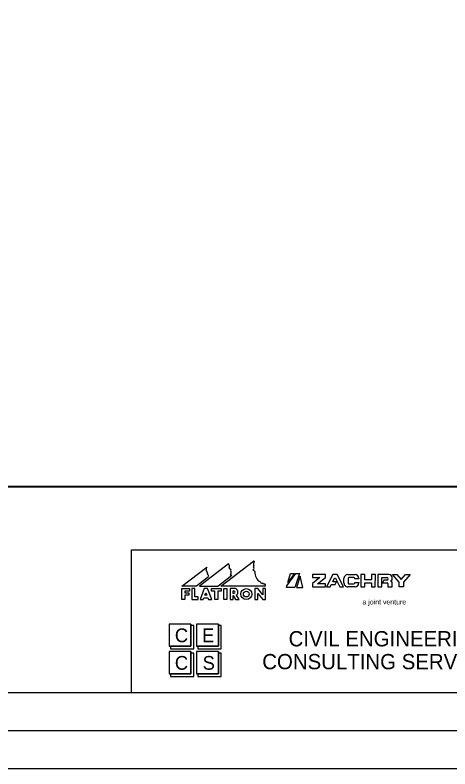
# Model space of a CAD drawing. Extents: x -2251 to 10196, y -13470 to 1199.
# Drawn here: x 3737.4 to 4022.4, y -4450.7 to -3956.7 of the extents above; entities that cross this region are included whole.
import ezdxf

# ---------------------------------------------------------------- set-up
doc = ezdxf.new("R2010")
doc.units = 0
for name, color, linetype in [('Level 3', 7, 'Continuous'), ('RD_SHT_Bndy', 7, 'Continuous'), ('RD_SHT_Iplotshp', 7, 'Continuous'), ('RD_SHT_Logo', 7, 'Continuous'), ('RD_SHT_Misc1', 7, 'Continuous'), ('RD_SHT_Snap', 7, 'Continuous'), ('RD_SHT_TX', 7, 'Continuous'), ('RD_TX_RoadID', 7, 'Continuous')]:
    doc.layers.add(name, color=color, linetype=linetype)

msp = doc.modelspace()

# ---------------------------------------------------------------- linework, layer by layer
at = {"layer": 'Level 3'}
msp.add_line((3965.07, -4363.99), (3965.07, -4363.99), dxfattribs=at)
msp.add_line((3965.07, -4363.99), (3965.07, -4363.99), dxfattribs=at)
msp.add_line((3965.07, -4363.99), (3965.07, -4363.99), dxfattribs=at)
msp.add_line((3965.07, -4363.99), (3965.07, -4363.99), dxfattribs=at)
at = {"layer": 'RD_SHT_Bndy'}
for p, q in [((2603.1, -4400.65), (4278.1, -4400.65)), ((4291.65, -4425.65), (2531.65, -4425.65)), ((4291.6, -4450.7), (2531.6, -4450.65))]:
    msp.add_line(p, q, dxfattribs=at)
msp.add_lwpolyline([(2653.4, -3401.26), (4231.08, -3401.26), (4231.08, -4265.57), (2653.4, -4265.57)], close=True, dxfattribs=at)
at = {"layer": 'RD_SHT_Iplotshp'}
msp.add_lwpolyline([(2496.65, -3325.65), (4296.65, -3325.65), (4296.65, -4425.65), (2496.65, -4425.65)], close=True, dxfattribs=at)
at = {"layer": 'RD_SHT_Logo'}
for p, q in [((3877.35, -4316.27), (3858.31, -4330.86)), ((3872.32, -4330.86), (3893.74, -4314.44)), ((3846.7, -4330.86), (3862.98, -4318.38)), ((3915.56, -4330.77), (3921.47, -4322.59)), ((3920.48, -4322.59), (3916.24, -4328.47)), ((3916.24, -4328.47), (3917.96, -4322.59)), ((3917.96, -4322.59), (3920.48, -4322.59)), ((3923.82, -4322.59), (3920.68, -4331.76)), ((3921.47, -4322.59), (3923.82, -4322.59)), ((3864.27, -4324.74), (3856.29, -4330.86)), ((3870.3, -4330.86), (3879.48, -4323.82)), ((3924.24, -4324.44), (3921.74, -4331.76)), ((3925.99, -4331.76), (3924.24, -4324.44)), ((3940.93, -4323.35), (3932.22, -4323.35)), ((3932.22, -4323.35), (3932.22, -4325.3)), ((3937.2, -4325.3), (3932.22, -4329.24)), ((3932.22, -4325.3), (3937.2, -4325.3)), ((3935.63, -4329.35), (3940.93, -4325.16)), ((3940.93, -4325.16), (3940.93, -4323.35)), ((3945.58, -4323.35), (3941.53, -4331.3)), ((3945.57, -4327.99), (3946.71, -4325.75)), ((3948.58, -4323.35), (3945.58, -4323.35)), ((3946.71, -4325.75), (3947.44, -4325.75)), ((3947.44, -4325.75), (3950.27, -4331.3)), ((3952.63, -4331.3), (3948.58, -4323.35)), ((3952.94, -4328.8), (3952.94, -4325.85)), ((3955.44, -4323.35), (3960.18, -4323.35)), ((3955.64, -4325.8), (3955.64, -4328.85)), ((3959.48, -4325.3), (3956.14, -4325.3)), ((3959.98, -4326.15), (3959.98, -4325.8)), ((3962.68, -4326.15), (3959.98, -4326.15)), ((3962.68, -4325.85), (3962.68, -4326.15)), ((3966.62, -4323.35), (3964.02, -4323.35)), ((3964.02, -4323.35), (3964.02, -4331.3)), ((3966.62, -4326.8), (3966.62, -4323.35)), ((3970.9, -4326.8), (3966.62, -4326.8)), ((3970.9, -4323.35), (3970.9, -4326.8)), ((3973.51, -4323.35), (3970.9, -4323.35)), ((3973.5, -4331.3), (3973.51, -4323.35)), ((3982.43, -4323.35), (3975.13, -4323.35)), ((3975.13, -4323.35), (3975.13, -4331.3)), ((3977.83, -4331.3), (3977.83, -4325.31)), ((3977.83, -4325.31), (3981.07, -4325.31)), ((3979.03, -4326.97), (3978.11, -4328.77)), ((3981.07, -4326.97), (3979.03, -4326.97)), ((3983.68, -4327.6), (3983.68, -4327.47)), ((3984.43, -4326.36), (3984.43, -4325.35)), ((3984.68, -4323.35), (3987.64, -4323.35)), ((3989.08, -4328.24), (3984.68, -4323.35)), ((3987.64, -4323.35), (3990.48, -4326.51)), ((3990.48, -4326.51), (3993.32, -4323.35)), ((3996.28, -4323.35), (3991.88, -4328.24)), ((3993.32, -4323.35), (3996.28, -4323.35)), ((3856.29, -4330.86), (3846.7, -4330.86)), ((3846.72, -4339.7), (3846.72, -4332.5)), ((3846.72, -4332.5), (3851.82, -4332.5)), ((3851.82, -4332.5), (3851.82, -4334.15)), ((3855.12, -4332.5), (3853.17, -4332.5)), ((3853.17, -4332.5), (3853.17, -4339.7)), ((3855.12, -4337.9), (3855.12, -4332.5)), ((3858.31, -4330.86), (3870.3, -4330.86)), ((3861.42, -4332.5), (3858.65, -4339.71)), ((3863.52, -4332.5), (3861.42, -4332.5)), ((3866.28, -4339.71), (3863.52, -4332.5)), ((3866.22, -4334.15), (3866.22, -4332.5)), ((3866.22, -4332.5), (3872.37, -4332.5)), ((3901.19, -4330.86), (3872.32, -4330.86)), ((3872.37, -4332.5), (3872.37, -4334.15)), ((3874.17, -4339.71), (3874.17, -4332.5)), ((3874.17, -4332.5), (3876.12, -4332.5)), ((3876.12, -4332.5), (3876.12, -4339.71)), ((3881.8, -4332.5), (3878.38, -4332.5)), ((3878.38, -4332.5), (3878.38, -4339.71)), ((3896.52, -4332.5), (3894.57, -4332.5)), ((3894.57, -4332.5), (3894.57, -4339.71)), ((3899.67, -4336.53), (3896.52, -4332.5)), ((3901.62, -4332.5), (3899.67, -4332.5)), ((3899.67, -4332.5), (3899.67, -4336.53)), ((3901.62, -4339.71), (3901.62, -4332.5)), ((3915.27, -4331.76), (3915.56, -4330.77)), ((3920.68, -4331.76), (3915.27, -4331.76)), ((3921.74, -4331.76), (3925.99, -4331.76)), ((3932.22, -4329.24), (3932.22, -4331.3)), ((3932.22, -4331.3), (3940.93, -4331.3)), ((3940.93, -4329.35), (3935.63, -4329.35)), ((3940.93, -4331.3), (3940.93, -4329.35)), ((3941.53, -4331.3), (3943.88, -4331.3)), ((3943.88, -4331.3), (3944.65, -4329.79)), ((3944.65, -4329.79), (3947.23, -4329.79)), ((3948.15, -4327.99), (3945.57, -4327.99)), ((3947.23, -4329.79), (3948.15, -4327.99)), ((3950.27, -4331.3), (3952.63, -4331.3)), ((3960.18, -4331.3), (3955.44, -4331.3)), ((3956.14, -4329.35), (3959.48, -4329.35)), ((3959.98, -4328.5), (3962.68, -4328.5)), ((3959.98, -4328.85), (3959.98, -4328.5)), ((3962.68, -4328.5), (3962.68, -4328.8)), ((3964.02, -4331.3), (3966.62, -4331.3)), ((3966.62, -4331.3), (3966.62, -4328.8)), ((3966.62, -4328.8), (3970.9, -4328.8)), ((3970.9, -4328.8), (3970.9, -4331.3)), ((3970.9, -4331.3), (3973.5, -4331.3)), ((3975.13, -4331.3), (3977.83, -4331.3)), ((3978.11, -4328.77), (3981.24, -4328.77)), ((3981.74, -4329.27), (3981.74, -4331.3)), ((3981.74, -4331.3), (3984.54, -4331.3)), ((3984.54, -4331.3), (3984.54, -4328.76)), ((3989.08, -4331.3), (3989.08, -4328.24)), ((3991.88, -4331.3), (3989.08, -4331.3)), ((3991.88, -4328.24), (3991.88, -4331.3)), ((3851.82, -4334.15), (3848.67, -4334.15)), ((3848.67, -4334.15), (3848.67, -4335.21)), ((3848.67, -4335.21), (3851.22, -4335.21)), ((3851.22, -4336.86), (3848.67, -4336.86)), ((3848.67, -4336.86), (3848.67, -4339.7)), ((3851.22, -4335.21), (3851.22, -4336.86)), ((3861.83, -4336.86), (3862.47, -4335.2)), ((3863.1, -4336.86), (3861.83, -4336.86)), ((3862.47, -4335.2), (3863.1, -4336.86)), ((3868.32, -4334.15), (3866.22, -4334.15)), ((3868.32, -4339.71), (3868.32, -4334.15)), ((3872.37, -4334.15), (3870.27, -4334.15)), ((3870.27, -4334.15), (3870.27, -4339.71)), ((3880.33, -4335.66), (3880.33, -4334.01)), ((3880.33, -4339.71), (3880.33, -4337.02)), ((3880.33, -4337.02), (3881.94, -4339.71)), ((3884.16, -4339.71), (3882.43, -4336.82)), ((3896.52, -4339.71), (3896.52, -4335.67)), ((3896.52, -4335.67), (3899.67, -4339.71)), ((3848.67, -4339.7), (3846.72, -4339.7)), ((3853.17, -4339.7), (3857.37, -4339.71)), ((3857.37, -4337.9), (3855.12, -4337.9)), ((3857.37, -4339.71), (3857.37, -4337.9)), ((3858.65, -4339.71), (3860.74, -4339.71)), ((3860.74, -4339.71), (3861.2, -4338.51)), ((3861.2, -4338.51), (3863.74, -4338.51)), ((3863.74, -4338.51), (3864.2, -4339.71)), ((3864.2, -4339.71), (3866.28, -4339.71)), ((3870.27, -4339.71), (3868.32, -4339.71)), ((3876.12, -4339.71), (3874.17, -4339.71)), ((3878.38, -4339.71), (3880.33, -4339.71)), ((3881.94, -4339.71), (3884.16, -4339.71)), ((3894.57, -4339.71), (3896.52, -4339.71)), ((3899.67, -4339.71), (3901.62, -4339.71)), ((3852.67, -4355.79), (3838.28, -4355.79)), ((3838.28, -4355.79), (3838.28, -4370.23)), ((3852.67, -4370.23), (3852.67, -4355.79)), ((3852.67, -4355.79), (3852.67, -4370.23)), ((3854.48, -4356.7), (3852.67, -4356.7)), ((3854.48, -4372.03), (3854.48, -4356.7)), ((3870.67, -4355.79), (3856.27, -4355.79)), ((3856.27, -4355.79), (3856.27, -4370.23)), ((3870.67, -4370.23), (3870.67, -4355.79)), ((3870.67, -4355.79), (3870.67, -4370.23)), ((3872.48, -4356.7), (3870.67, -4356.7)), ((3872.48, -4372.03), (3872.48, -4356.7)), ((3838.28, -4370.23), (3852.67, -4370.23)), ((3852.67, -4370.23), (3839.17, -4370.23)), ((3839.17, -4370.23), (3839.17, -4372.03)), ((3839.17, -4372.03), (3854.48, -4372.03)), ((3856.27, -4370.23), (3870.67, -4370.23)), ((3870.67, -4370.23), (3857.18, -4370.23)), ((3857.18, -4370.23), (3857.18, -4372.03)), ((3857.18, -4372.03), (3872.48, -4372.03)), ((3852.67, -4373.84), (3838.28, -4373.84)), ((3838.28, -4373.84), (3838.28, -4388.27)), ((3852.67, -4388.27), (3852.67, -4373.84)), ((3852.67, -4373.84), (3852.67, -4388.27)), ((3854.48, -4374.74), (3852.67, -4374.74)), ((3854.48, -4390.07), (3854.48, -4374.74)), ((3870.67, -4373.84), (3856.27, -4373.84)), ((3856.27, -4373.84), (3856.27, -4388.27)), ((3870.67, -4388.27), (3870.67, -4373.84)), ((3870.67, -4373.84), (3870.67, -4388.27)), ((3872.48, -4374.74), (3870.67, -4374.74)), ((3872.48, -4390.07), (3872.48, -4374.74)), ((3838.28, -4388.27), (3852.67, -4388.27)), ((3852.67, -4388.27), (3839.17, -4388.27)), ((3839.17, -4388.27), (3839.17, -4390.07)), ((3839.17, -4390.07), (3854.48, -4390.07)), ((3856.27, -4388.27), (3870.67, -4388.27)), ((3870.67, -4388.27), (3857.18, -4388.27)), ((3857.18, -4388.27), (3857.18, -4390.07)), ((3857.18, -4390.07), (3872.48, -4390.07))]:
    msp.add_line(p, q, dxfattribs=at)
for radius in [3.6, 1.9]:
    msp.add_circle((3888.95, -4336.1), radius, dxfattribs=at)
for centre, radius, start, end in [((3875.05, -4318.02), 2.89, 342.0343, 37.2653), ((3893.13, -4317.66), 0.749, 309.4079, 17.0499), ((3897.87, -4316.34), 4.17, 156.4699, 195.3053), ((3893.86, -4314.6), 0.2, 336.4699, 127.4657), ((3866.29, -4320.12), 3.74, 152.2252, 185.8662), ((3862.1, -4321.62), 1.21, 351.6466, 67.1294), ((3864.29, -4321.94), 1, 171.6466, 221.9371), ((3863.11, -4323.01), 0.592, 327.6019, 41.9371), ((3877.99, -4318.97), 0.2, 162.0343, 220.8638), ((3876.86, -4319.95), 1.3, 11.8745, 40.8638), ((3878.32, -4319.64), 0.2, 191.8745, 279.8173), ((3878.44, -4320.33), 0.499, 44.4799, 99.8173), ((3875.8, -4322.18), 3.16, 331.2486, 18.4584), ((3879.5, -4320.72), 0.843, 144.641, 212.5499), ((3878.65, -4320.12), 0.2, 324.641, 44.4799), ((3893.57, -4320.5), 0.2, 133.0036, 262.3069), ((3891.59, -4318.37), 2.7, 313.0036, 343.6807), ((3893.73, -4318.39), 0.2, 129.4079, 246.863), ((3893.31, -4322.44), 1.76, 45.283, 82.3069), ((3893.27, -4319.47), 0.973, 20.4113, 66.863), ((3894.4, -4321.33), 0.2, 353.8329, 45.283), ((3901.36, -4322.08), 6.8, 173.8329, 242.3928), ((3863.3, -4324.33), 1.05, 337.4201, 73.1261), ((3878.92, -4324.44), 0.827, 48.0701, 115.7229), ((3955.44, -4325.85), 2.5, 89.9984, 179.9984), ((3956.14, -4325.8), 0.5, 89.9984, 179.9984), ((3959.48, -4325.8), 0.5, 359.9984, 89.9984), ((3960.18, -4325.85), 2.5, 359.9984, 89.9984), ((3981.07, -4326.14), 0.831, 269.9984, 89.9984), ((3982.43, -4325.35), 2, 359.9984, 89.9984), ((3983.23, -4326.36), 1.2, 291.95, 359.9984), ((3983.34, -4328.76), 1.2, 359.9984, 73.7977), ((3898.12, -4328.28), 0.2, 9.0833, 62.3928), ((3899.35, -4328.09), 1.04, 189.0833, 295.769), ((3899.89, -4329.21), 0.2, 33.7112, 115.769), ((3900.89, -4328.54), 1.01, 213.7112, 268.6299), ((3900.86, -4329.74), 0.2, 78.9712, 88.6299), ((3900.75, -4330.3), 0.767, 320.912, 78.9712), ((3901.19, -4330.66), 0.2, 269.9984, 320.912), ((3955.44, -4328.8), 2.5, 179.9984, 269.9984), ((3956.14, -4328.85), 0.5, 179.9984, 269.9984), ((3959.48, -4328.85), 0.5, 269.9984, 359.9984), ((3960.18, -4328.8), 2.5, 269.9984, 359.9984), ((3981.24, -4329.27), 0.5, 359.9984, 89.9984)]:
    msp.add_arc(centre, radius, start, end, dxfattribs=at)
msp.add_ellipse((3880.33, -4334.83), major_axis=(1.36, 0), ratio=0.609965, start_param=4.712389, end_param=7.853982, dxfattribs=at)
msp.add_open_spline([(3882.43, -4336.82), (3882.51, -4336.76), (3882.59, -4336.7), (3882.81, -4336.49), (3882.95, -4336.34), (3883.13, -4336.07), (3883.19, -4335.97), (3883.29, -4335.77), (3883.34, -4335.66), (3883.41, -4335.44), (3883.44, -4335.32), (3883.47, -4335.08), (3883.48, -4334.96), (3883.48, -4334.71), (3883.47, -4334.59), (3883.44, -4334.35), (3883.41, -4334.23), (3883.34, -4334.01), (3883.29, -4333.9), (3883.19, -4333.7), (3883.13, -4333.6), (3882.95, -4333.33), (3882.81, -4333.18), (3882.52, -4332.91), (3882.37, -4332.8), (3882.08, -4332.63), (3881.94, -4332.56), (3881.8, -4332.5)], degree=3, dxfattribs=at)
at = {"layer": 'RD_SHT_Misc1'}
msp.add_lwpolyline([(4296.65, -4425.65), (4296.68, -3325.65), (2596.68, -3325.6), (2596.65, -4425.6)], close=True, dxfattribs=at)
at = {"layer": 'RD_SHT_Snap'}
msp.add_lwpolyline([(2508.15, -3325.65), (4308.15, -3325.65), (4308.15, -4425.65), (2508.15, -4425.65)], close=True, dxfattribs=at)
at = {"layer": 'RD_SHT_TX'}
for p, q in [((3813.76, -4400.65), (3813.76, -4307.15)), ((3813.76, -4400.65), (3813.76, -4307.15)), ((3813.76, -4307.15), (4278.1, -4307.15))]:
    msp.add_line(p, q, dxfattribs=at)
at = {"layer": 'RD_TX_RoadID'}
msp.add_lwpolyline([(2650.54, -4265.73), (4233.93, -4265.73), (4233.93, -3462.61), (2650.54, -3462.61)], close=True, dxfattribs=at)

# ---------------------------------------------------------------- texts
at = {"layer": 'RD_SHT_Logo'}
msp.add_text('a joint venture', height=3.3, rotation=359.9984, dxfattribs=at).set_placement((3965.08, -4342.93))
for s, height, p in [('C', 9.02, (3842.11, -4367.66)), ('E', 9.02, (3859.9, -4367.66)), ('CIVIL ENGINEERING', 10, (3916.67, -4370.38)), ('C', 9.02, (3842.11, -4385.71)), ('S', 9.02, (3860.32, -4385.71)), ('CONSULTING SERVICES, INC.', 10, (3899.39, -4385.38))]:
    msp.add_text(s, height=height, dxfattribs=at).set_placement(p)

doc.saveas('drawing.dxf')
